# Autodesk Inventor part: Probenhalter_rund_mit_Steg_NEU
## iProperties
Shininess: 64.0
Length Units: 11269
Angle Units: 11279
Time Units: 11290
Mass Units: 11283
Length Display Precision: 3
Angle Display Precision: 2
Compacted: True
Part Number: Probenhalter_rund_mit_Steg_NEU
Document SubType Name: Modeling
Created: 2004-07
Material: Standard
Designer: STRAKA
Density: 0.0
Volumn: 0.0
Area: 0.0
PropertySet Name: Model Information
Control State: 0
Master: False
Checked Out: False
Author: STRAKA
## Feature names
1. Grundkörper [Extrusion]
2. Absenkung der Fläche [Extrusion]
3. Nut innen [Extrusion]
4. Nuten innen links oben [Rectangular Pattern]
5. Nuten alle innen [Rectangular Pattern]
6. Nut außen [Extrusion]
7. Nuten außen links oben [Rectangular Pattern]
8. Nuten außen alle [Rectangular Pattern]
9. Extrusion7
10. Rechteckige Anordnung6 [Rectangular Pattern]
